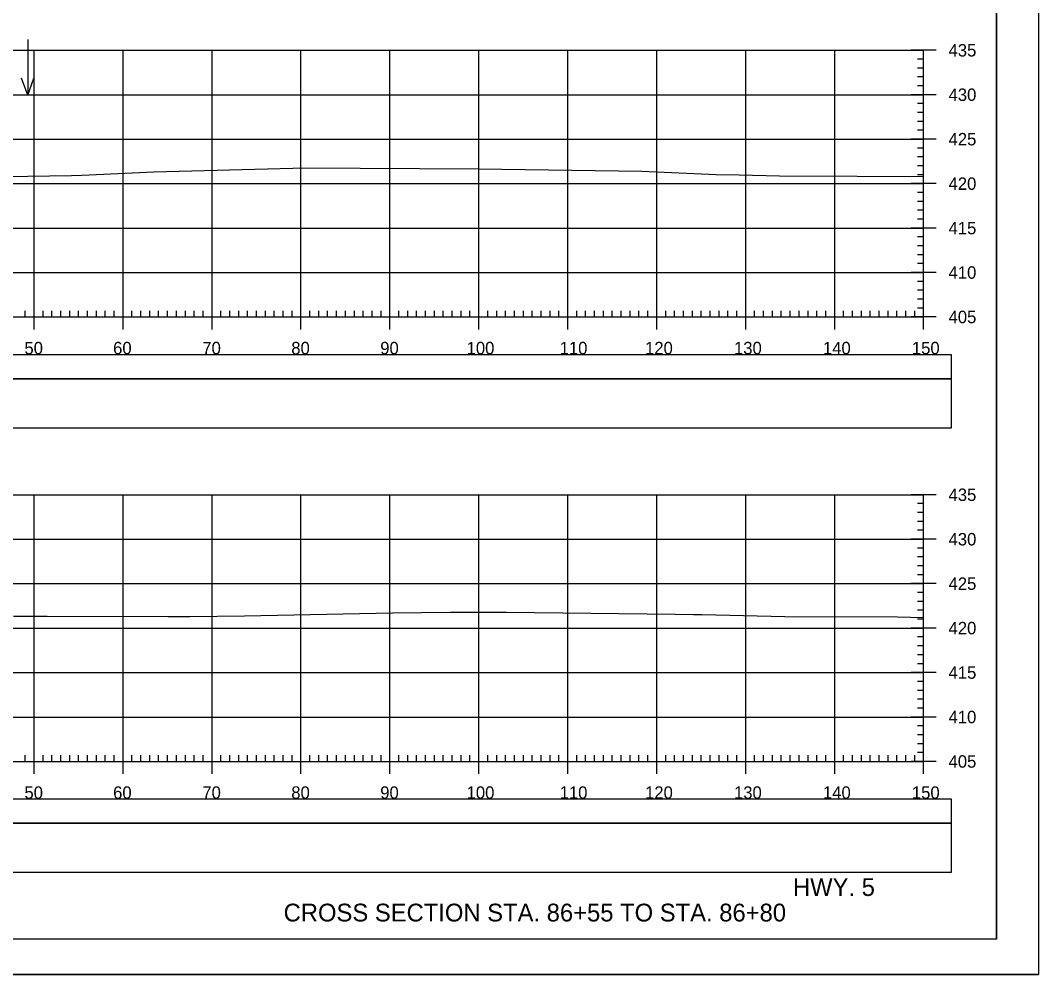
# Model space of a CAD drawing. Extents: x 1371057 to 1372761, y 380005 to 390517.
# Drawn here: x 1371276 to 1371390.5, y 388325.3 to 388432.6 of the extents above; entities that cross this region are included whole.
import ezdxf

# ---------------------------------------------------------------- set-up
doc = ezdxf.new("R2010")
doc.units = 0
for name, color, linetype in [('R_Axis', 7, 'Continuous'), ('R_Axis Annot', 7, 'Continuous'), ('R_Border', 7, 'Continuous'), ('R_Detour', 7, 'Continuous'), ('R_Dimension', 7, 'Continuous'), ('R_Draft', 7, 'Continuous'), ('R_Exist Surface', 7, 'Continuous'), ('R_Grid', 7, 'Continuous'), ('R_No Plot', 7, 'Continuous'), ('R_Water Annot', 7, 'Continuous')]:
    doc.layers.add(name, color=color, linetype=linetype)

msp = doc.modelspace()

# ---------------------------------------------------------------- linework, layer by layer
at = {"layer": 'R_Axis'}
for p, q in [((1371378.93, 388429.24), (1371376.13, 388429.24)), ((1371377.53, 388399.24), (1371377.53, 388429.24)), ((1371377.53, 388428.24), (1371376.83, 388428.24)), ((1371377.53, 388427.24), (1371376.83, 388427.24)), ((1371377.53, 388426.24), (1371376.83, 388426.24)), ((1371377.53, 388425.24), (1371376.83, 388425.24)), ((1371378.93, 388424.24), (1371376.13, 388424.24)), ((1371377.53, 388423.24), (1371376.83, 388423.24)), ((1371377.53, 388422.24), (1371376.83, 388422.24)), ((1371377.53, 388421.24), (1371376.83, 388421.24)), ((1371377.53, 388420.24), (1371376.83, 388420.24)), ((1371378.93, 388419.24), (1371376.13, 388419.24)), ((1371377.53, 388418.24), (1371376.83, 388418.24)), ((1371377.53, 388417.24), (1371376.83, 388417.24)), ((1371377.53, 388416.24), (1371376.83, 388416.24)), ((1371378.93, 388414.24), (1371376.13, 388414.24)), ((1371377.53, 388415.24), (1371376.83, 388415.24)), ((1371377.53, 388413.24), (1371376.83, 388413.24)), ((1371377.53, 388412.24), (1371376.83, 388412.24)), ((1371377.53, 388411.24), (1371376.83, 388411.24)), ((1371377.53, 388410.24), (1371376.83, 388410.24)), ((1371378.93, 388409.24), (1371376.13, 388409.24)), ((1371377.53, 388408.24), (1371376.83, 388408.24)), ((1371377.53, 388407.24), (1371376.83, 388407.24)), ((1371377.53, 388406.24), (1371376.83, 388406.24)), ((1371377.53, 388405.24), (1371376.83, 388405.24)), ((1371378.93, 388404.24), (1371376.13, 388404.24)), ((1371377.53, 388403.24), (1371376.83, 388403.24)), ((1371377.53, 388402.24), (1371376.83, 388402.24)), ((1371277.53, 388397.84), (1371277.53, 388400.64)), ((1371287.53, 388397.84), (1371287.53, 388400.64)), ((1371297.53, 388397.84), (1371297.53, 388400.64)), ((1371307.53, 388397.84), (1371307.53, 388400.64)), ((1371317.53, 388397.84), (1371317.53, 388400.64)), ((1371327.53, 388397.84), (1371327.53, 388400.64)), ((1371337.53, 388397.84), (1371337.53, 388400.64)), ((1371347.53, 388397.84), (1371347.53, 388400.64)), ((1371357.53, 388397.84), (1371357.53, 388400.64)), ((1371367.53, 388397.84), (1371367.53, 388400.64)), ((1371377.53, 388401.24), (1371376.83, 388401.24)), ((1371377.53, 388397.84), (1371377.53, 388400.64)), ((1371276.53, 388399.24), (1371276.53, 388399.94)), ((1371278.53, 388399.24), (1371278.53, 388399.94)), ((1371279.53, 388399.24), (1371279.53, 388399.94)), ((1371280.53, 388399.24), (1371280.53, 388399.94)), ((1371281.53, 388399.24), (1371281.53, 388399.94)), ((1371282.53, 388399.24), (1371282.53, 388399.94)), ((1371283.53, 388399.24), (1371283.53, 388399.94)), ((1371284.53, 388399.24), (1371284.53, 388399.94)), ((1371285.53, 388399.24), (1371285.53, 388399.94)), ((1371286.53, 388399.24), (1371286.53, 388399.94)), ((1371288.53, 388399.24), (1371288.53, 388399.94)), ((1371289.53, 388399.24), (1371289.53, 388399.94)), ((1371290.53, 388399.24), (1371290.53, 388399.94)), ((1371291.53, 388399.24), (1371291.53, 388399.94)), ((1371292.53, 388399.24), (1371292.53, 388399.94)), ((1371293.53, 388399.24), (1371293.53, 388399.94)), ((1371294.53, 388399.24), (1371294.53, 388399.94)), ((1371295.53, 388399.24), (1371295.53, 388399.94)), ((1371296.53, 388399.24), (1371296.53, 388399.94)), ((1371298.53, 388399.24), (1371298.53, 388399.94)), ((1371299.53, 388399.24), (1371299.53, 388399.94)), ((1371300.53, 388399.24), (1371300.53, 388399.94)), ((1371301.53, 388399.24), (1371301.53, 388399.94)), ((1371302.53, 388399.24), (1371302.53, 388399.94)), ((1371303.53, 388399.24), (1371303.53, 388399.94)), ((1371304.53, 388399.24), (1371304.53, 388399.94)), ((1371305.53, 388399.24), (1371305.53, 388399.94)), ((1371306.53, 388399.24), (1371306.53, 388399.94)), ((1371308.53, 388399.24), (1371308.53, 388399.94)), ((1371309.53, 388399.24), (1371309.53, 388399.94)), ((1371310.53, 388399.24), (1371310.53, 388399.94)), ((1371311.53, 388399.24), (1371311.53, 388399.94)), ((1371312.53, 388399.24), (1371312.53, 388399.94)), ((1371313.53, 388399.24), (1371313.53, 388399.94)), ((1371314.53, 388399.24), (1371314.53, 388399.94)), ((1371315.53, 388399.24), (1371315.53, 388399.94)), ((1371316.53, 388399.24), (1371316.53, 388399.94)), ((1371318.53, 388399.24), (1371318.53, 388399.94)), ((1371319.53, 388399.24), (1371319.53, 388399.94)), ((1371320.53, 388399.24), (1371320.53, 388399.94)), ((1371321.53, 388399.24), (1371321.53, 388399.94)), ((1371322.53, 388399.24), (1371322.53, 388399.94)), ((1371323.53, 388399.24), (1371323.53, 388399.94)), ((1371324.53, 388399.24), (1371324.53, 388399.94)), ((1371325.53, 388399.24), (1371325.53, 388399.94)), ((1371326.53, 388399.24), (1371326.53, 388399.94)), ((1371328.53, 388399.24), (1371328.53, 388399.94)), ((1371329.53, 388399.24), (1371329.53, 388399.94)), ((1371330.53, 388399.24), (1371330.53, 388399.94)), ((1371331.53, 388399.24), (1371331.53, 388399.94)), ((1371332.53, 388399.24), (1371332.53, 388399.94)), ((1371333.53, 388399.24), (1371333.53, 388399.94)), ((1371334.53, 388399.24), (1371334.53, 388399.94)), ((1371335.53, 388399.24), (1371335.53, 388399.94)), ((1371336.53, 388399.24), (1371336.53, 388399.94)), ((1371338.53, 388399.24), (1371338.53, 388399.94)), ((1371339.53, 388399.24), (1371339.53, 388399.94)), ((1371340.53, 388399.24), (1371340.53, 388399.94)), ((1371341.53, 388399.24), (1371341.53, 388399.94)), ((1371342.53, 388399.24), (1371342.53, 388399.94)), ((1371343.53, 388399.24), (1371343.53, 388399.94)), ((1371344.53, 388399.24), (1371344.53, 388399.94)), ((1371345.53, 388399.24), (1371345.53, 388399.94)), ((1371346.53, 388399.24), (1371346.53, 388399.94)), ((1371348.53, 388399.24), (1371348.53, 388399.94)), ((1371349.53, 388399.24), (1371349.53, 388399.94)), ((1371350.53, 388399.24), (1371350.53, 388399.94)), ((1371351.53, 388399.24), (1371351.53, 388399.94)), ((1371352.53, 388399.24), (1371352.53, 388399.94)), ((1371353.53, 388399.24), (1371353.53, 388399.94)), ((1371354.53, 388399.24), (1371354.53, 388399.94)), ((1371355.53, 388399.24), (1371355.53, 388399.94)), ((1371356.53, 388399.24), (1371356.53, 388399.94)), ((1371358.53, 388399.24), (1371358.53, 388399.94)), ((1371359.53, 388399.24), (1371359.53, 388399.94)), ((1371360.53, 388399.24), (1371360.53, 388399.94)), ((1371361.53, 388399.24), (1371361.53, 388399.94)), ((1371362.53, 388399.24), (1371362.53, 388399.94)), ((1371363.53, 388399.24), (1371363.53, 388399.94)), ((1371364.53, 388399.24), (1371364.53, 388399.94)), ((1371365.53, 388399.24), (1371365.53, 388399.94)), ((1371366.53, 388399.24), (1371366.53, 388399.94)), ((1371368.53, 388399.24), (1371368.53, 388399.94)), ((1371369.53, 388399.24), (1371369.53, 388399.94)), ((1371370.53, 388399.24), (1371370.53, 388399.94)), ((1371371.53, 388399.24), (1371371.53, 388399.94)), ((1371372.53, 388399.24), (1371372.53, 388399.94)), ((1371373.53, 388399.24), (1371373.53, 388399.94)), ((1371374.53, 388399.24), (1371374.53, 388399.94)), ((1371375.53, 388399.24), (1371375.53, 388399.94)), ((1371376.53, 388399.24), (1371376.53, 388399.94)), ((1371377.53, 388400.24), (1371376.83, 388400.24)), ((1371077.53, 388399.24), (1371377.53, 388399.24)), ((1371378.93, 388399.24), (1371376.13, 388399.24)), ((1371378.93, 388379.24), (1371376.13, 388379.24)), ((1371377.53, 388349.24), (1371377.53, 388379.24)), ((1371377.53, 388378.24), (1371376.83, 388378.24)), ((1371377.53, 388377.24), (1371376.83, 388377.24)), ((1371377.53, 388376.24), (1371376.83, 388376.24)), ((1371378.93, 388374.24), (1371376.13, 388374.24)), ((1371377.53, 388375.24), (1371376.83, 388375.24)), ((1371377.53, 388373.24), (1371376.83, 388373.24)), ((1371377.53, 388372.24), (1371376.83, 388372.24)), ((1371377.53, 388371.24), (1371376.83, 388371.24)), ((1371377.53, 388370.24), (1371376.83, 388370.24)), ((1371378.93, 388369.24), (1371376.13, 388369.24)), ((1371377.53, 388368.24), (1371376.83, 388368.24)), ((1371377.53, 388367.24), (1371376.83, 388367.24)), ((1371377.53, 388366.24), (1371376.83, 388366.24)), ((1371377.53, 388365.24), (1371376.83, 388365.24)), ((1371378.93, 388364.24), (1371376.13, 388364.24)), ((1371377.53, 388363.24), (1371376.83, 388363.24)), ((1371377.53, 388362.24), (1371376.83, 388362.24)), ((1371377.53, 388361.24), (1371376.83, 388361.24)), ((1371377.53, 388360.24), (1371376.83, 388360.24)), ((1371378.93, 388359.24), (1371376.13, 388359.24)), ((1371377.53, 388358.24), (1371376.83, 388358.24)), ((1371377.53, 388357.24), (1371376.83, 388357.24)), ((1371377.53, 388356.24), (1371376.83, 388356.24)), ((1371377.53, 388355.24), (1371376.83, 388355.24)), ((1371378.93, 388354.24), (1371376.13, 388354.24)), ((1371377.53, 388353.24), (1371376.83, 388353.24)), ((1371377.53, 388352.24), (1371376.83, 388352.24)), ((1371277.53, 388347.84), (1371277.53, 388350.64)), ((1371287.53, 388347.84), (1371287.53, 388350.64)), ((1371297.53, 388347.84), (1371297.53, 388350.64)), ((1371307.53, 388347.84), (1371307.53, 388350.64)), ((1371317.53, 388347.84), (1371317.53, 388350.64)), ((1371327.53, 388347.84), (1371327.53, 388350.64)), ((1371337.53, 388347.84), (1371337.53, 388350.64)), ((1371347.53, 388347.84), (1371347.53, 388350.64)), ((1371357.53, 388347.84), (1371357.53, 388350.64)), ((1371367.53, 388347.84), (1371367.53, 388350.64)), ((1371377.53, 388351.24), (1371376.83, 388351.24)), ((1371377.53, 388350.24), (1371376.83, 388350.24)), ((1371377.53, 388347.84), (1371377.53, 388350.64)), ((1371077.53, 388349.24), (1371377.53, 388349.24)), ((1371276.53, 388349.24), (1371276.53, 388349.94)), ((1371278.53, 388349.24), (1371278.53, 388349.94)), ((1371279.53, 388349.24), (1371279.53, 388349.94)), ((1371280.53, 388349.24), (1371280.53, 388349.94)), ((1371281.53, 388349.24), (1371281.53, 388349.94)), ((1371282.53, 388349.24), (1371282.53, 388349.94)), ((1371283.53, 388349.24), (1371283.53, 388349.94)), ((1371284.53, 388349.24), (1371284.53, 388349.94)), ((1371285.53, 388349.24), (1371285.53, 388349.94)), ((1371286.53, 388349.24), (1371286.53, 388349.94)), ((1371288.53, 388349.24), (1371288.53, 388349.94)), ((1371289.53, 388349.24), (1371289.53, 388349.94)), ((1371290.53, 388349.24), (1371290.53, 388349.94)), ((1371291.53, 388349.24), (1371291.53, 388349.94)), ((1371292.53, 388349.24), (1371292.53, 388349.94)), ((1371293.53, 388349.24), (1371293.53, 388349.94)), ((1371294.53, 388349.24), (1371294.53, 388349.94)), ((1371295.53, 388349.24), (1371295.53, 388349.94)), ((1371296.53, 388349.24), (1371296.53, 388349.94)), ((1371298.53, 388349.24), (1371298.53, 388349.94)), ((1371299.53, 388349.24), (1371299.53, 388349.94)), ((1371300.53, 388349.24), (1371300.53, 388349.94)), ((1371301.53, 388349.24), (1371301.53, 388349.94)), ((1371302.53, 388349.24), (1371302.53, 388349.94)), ((1371303.53, 388349.24), (1371303.53, 388349.94)), ((1371304.53, 388349.24), (1371304.53, 388349.94)), ((1371305.53, 388349.24), (1371305.53, 388349.94)), ((1371306.53, 388349.24), (1371306.53, 388349.94)), ((1371308.53, 388349.24), (1371308.53, 388349.94)), ((1371309.53, 388349.24), (1371309.53, 388349.94)), ((1371310.53, 388349.24), (1371310.53, 388349.94)), ((1371311.53, 388349.24), (1371311.53, 388349.94)), ((1371312.53, 388349.24), (1371312.53, 388349.94)), ((1371313.53, 388349.24), (1371313.53, 388349.94)), ((1371314.53, 388349.24), (1371314.53, 388349.94)), ((1371315.53, 388349.24), (1371315.53, 388349.94)), ((1371316.53, 388349.24), (1371316.53, 388349.94)), ((1371318.53, 388349.24), (1371318.53, 388349.94)), ((1371319.53, 388349.24), (1371319.53, 388349.94)), ((1371320.53, 388349.24), (1371320.53, 388349.94)), ((1371321.53, 388349.24), (1371321.53, 388349.94)), ((1371322.53, 388349.24), (1371322.53, 388349.94)), ((1371323.53, 388349.24), (1371323.53, 388349.94)), ((1371324.53, 388349.24), (1371324.53, 388349.94)), ((1371325.53, 388349.24), (1371325.53, 388349.94)), ((1371326.53, 388349.24), (1371326.53, 388349.94)), ((1371328.53, 388349.24), (1371328.53, 388349.94)), ((1371329.53, 388349.24), (1371329.53, 388349.94)), ((1371330.53, 388349.24), (1371330.53, 388349.94)), ((1371331.53, 388349.24), (1371331.53, 388349.94)), ((1371332.53, 388349.24), (1371332.53, 388349.94)), ((1371333.53, 388349.24), (1371333.53, 388349.94)), ((1371334.53, 388349.24), (1371334.53, 388349.94)), ((1371335.53, 388349.24), (1371335.53, 388349.94)), ((1371336.53, 388349.24), (1371336.53, 388349.94)), ((1371338.53, 388349.24), (1371338.53, 388349.94)), ((1371339.53, 388349.24), (1371339.53, 388349.94)), ((1371340.53, 388349.24), (1371340.53, 388349.94)), ((1371341.53, 388349.24), (1371341.53, 388349.94)), ((1371342.53, 388349.24), (1371342.53, 388349.94)), ((1371343.53, 388349.24), (1371343.53, 388349.94)), ((1371344.53, 388349.24), (1371344.53, 388349.94)), ((1371345.53, 388349.24), (1371345.53, 388349.94)), ((1371346.53, 388349.24), (1371346.53, 388349.94)), ((1371348.53, 388349.24), (1371348.53, 388349.94)), ((1371349.53, 388349.24), (1371349.53, 388349.94)), ((1371350.53, 388349.24), (1371350.53, 388349.94)), ((1371351.53, 388349.24), (1371351.53, 388349.94)), ((1371352.53, 388349.24), (1371352.53, 388349.94)), ((1371353.53, 388349.24), (1371353.53, 388349.94)), ((1371354.53, 388349.24), (1371354.53, 388349.94)), ((1371355.53, 388349.24), (1371355.53, 388349.94)), ((1371356.53, 388349.24), (1371356.53, 388349.94)), ((1371358.53, 388349.24), (1371358.53, 388349.94)), ((1371359.53, 388349.24), (1371359.53, 388349.94)), ((1371360.53, 388349.24), (1371360.53, 388349.94)), ((1371361.53, 388349.24), (1371361.53, 388349.94)), ((1371362.53, 388349.24), (1371362.53, 388349.94)), ((1371363.53, 388349.24), (1371363.53, 388349.94)), ((1371364.53, 388349.24), (1371364.53, 388349.94)), ((1371365.53, 388349.24), (1371365.53, 388349.94)), ((1371366.53, 388349.24), (1371366.53, 388349.94)), ((1371368.53, 388349.24), (1371368.53, 388349.94)), ((1371369.53, 388349.24), (1371369.53, 388349.94)), ((1371370.53, 388349.24), (1371370.53, 388349.94)), ((1371371.53, 388349.24), (1371371.53, 388349.94)), ((1371372.53, 388349.24), (1371372.53, 388349.94)), ((1371373.53, 388349.24), (1371373.53, 388349.94)), ((1371374.53, 388349.24), (1371374.53, 388349.94)), ((1371375.53, 388349.24), (1371375.53, 388349.94)), ((1371378.93, 388349.24), (1371376.13, 388349.24)), ((1371376.53, 388349.24), (1371376.53, 388349.94))]:
    msp.add_line(p, q, dxfattribs=at)
at = {"layer": 'R_Border'}
for q in [(1371385.71, 388534.7), (1371069.53, 388329.24)]:
    msp.add_line((1371385.71, 388329.24), q, dxfattribs=at)
at = {"layer": 'R_Detour'}
for points in [[(1371074.37, 388392.29), (1371380.68, 388392.29), (1371380.68, 388394.99), (1371074.37, 388394.99)], [(1371074.37, 388342.29), (1371380.68, 388342.29), (1371380.68, 388344.99), (1371074.37, 388344.99)]]:
    msp.add_lwpolyline(points, close=True, dxfattribs=at)
at = {"layer": 'R_Dimension'}
for points in [[(1371074.37, 388386.77), (1371380.68, 388386.77), (1371380.68, 388392.29), (1371074.37, 388392.29)], [(1371074.37, 388336.77), (1371380.68, 388336.77), (1371380.68, 388342.29), (1371074.37, 388342.29)]]:
    msp.add_lwpolyline(points, close=True, dxfattribs=at)
at = {"layer": 'R_Exist Surface'}
for points in [[(1371274.4, 388415.03), (1371279.25, 388415.1), (1371281.72, 388415.16), (1371282.88, 388415.2), (1371290.98, 388415.58), (1371306.61, 388415.98), (1371307.54, 388416), (1371327.49, 388415.91), (1371345.84, 388415.63), (1371354.21, 388415.25), (1371356.78, 388415.23), (1371361.33, 388415.13), (1371370.06, 388415.09), (1371377.53, 388415.06)], [(1371275.21, 388365.58), (1371278.99, 388365.58), (1371292.57, 388365.54), (1371295.09, 388365.55), (1371301.17, 388365.63), (1371317.8, 388365.95), (1371324.33, 388366.02), (1371330.65, 388366.03), (1371349.59, 388365.79), (1371351.67, 388365.78), (1371352.63, 388365.76), (1371361.92, 388365.55), (1371374.61, 388365.51), (1371377.53, 388365.44)]]:
    msp.add_lwpolyline(points, dxfattribs=at)
at = {"layer": 'R_Grid'}
for p, q in [((1371077.53, 388429.24), (1371377.53, 388429.24)), ((1371277.53, 388399.24), (1371277.53, 388429.24)), ((1371287.53, 388399.24), (1371287.53, 388429.24)), ((1371297.53, 388399.24), (1371297.53, 388429.24)), ((1371307.53, 388399.24), (1371307.53, 388429.24)), ((1371317.53, 388399.24), (1371317.53, 388429.24)), ((1371327.53, 388399.24), (1371327.53, 388429.24)), ((1371337.53, 388399.24), (1371337.53, 388429.24)), ((1371347.53, 388399.24), (1371347.53, 388429.24)), ((1371357.53, 388399.24), (1371357.53, 388429.24)), ((1371367.53, 388399.24), (1371367.53, 388429.24)), ((1371377.53, 388399.24), (1371377.53, 388429.24)), ((1371077.53, 388424.24), (1371377.53, 388424.24)), ((1371077.53, 388419.24), (1371377.53, 388419.24)), ((1371077.53, 388414.24), (1371377.53, 388414.24)), ((1371077.53, 388409.24), (1371377.53, 388409.24)), ((1371077.53, 388404.24), (1371377.53, 388404.24)), ((1371077.53, 388399.24), (1371377.53, 388399.24)), ((1371077.53, 388379.24), (1371377.53, 388379.24)), ((1371277.53, 388349.24), (1371277.53, 388379.24)), ((1371287.53, 388349.24), (1371287.53, 388379.24)), ((1371297.53, 388349.24), (1371297.53, 388379.24)), ((1371307.53, 388349.24), (1371307.53, 388379.24)), ((1371317.53, 388349.24), (1371317.53, 388379.24)), ((1371327.53, 388349.24), (1371327.53, 388379.24)), ((1371337.53, 388349.24), (1371337.53, 388379.24)), ((1371347.53, 388349.24), (1371347.53, 388379.24)), ((1371357.53, 388349.24), (1371357.53, 388379.24)), ((1371367.53, 388349.24), (1371367.53, 388379.24)), ((1371377.53, 388349.24), (1371377.53, 388379.24)), ((1371077.53, 388374.24), (1371377.53, 388374.24)), ((1371077.53, 388369.24), (1371377.53, 388369.24)), ((1371077.53, 388364.24), (1371377.53, 388364.24)), ((1371077.53, 388359.24), (1371377.53, 388359.24)), ((1371077.53, 388354.24), (1371377.53, 388354.24)), ((1371077.53, 388349.24), (1371377.53, 388349.24))]:
    msp.add_line(p, q, dxfattribs=at)
at = {"layer": 'R_No Plot'}
msp.add_line((1371057.12, 388325.26), (1371390.46, 388325.26), dxfattribs=at)
for points in [[(1371057.12, 388538.6), (1371390.46, 388538.6), (1371390.46, 388325.26), (1371057.12, 388325.26)], [(1371303.45, 388534.7), (1371323.07, 388534.7), (1371323.07, 388524.82), (1371339.18, 388524.82), (1371362.38, 388524.82), (1371362.5, 388496.66), (1371385.71, 388496.66), (1371385.71, 388329.24), (1371069.53, 388329.24), (1371069.53, 388534.7)]]:
    msp.add_lwpolyline(points, close=True, dxfattribs=at)
at = {"layer": 'R_Water Annot'}
for p, q in [((1371276.81, 388430.47), (1371276.81, 388424.19)), ((1371276.81, 388424.19), (1371276.11, 388426.11)), ((1371276.81, 388424.19), (1371277.51, 388426.11))]:
    msp.add_line(p, q, dxfattribs=at)

# ---------------------------------------------------------------- texts
at = {"layer": 'R_Axis Annot'}
for s, p in [('435', (1371380.33, 388428.54)), ('430', (1371380.33, 388423.54)), ('425', (1371380.33, 388418.54)), ('420', (1371380.33, 388413.54)), ('415', (1371380.33, 388408.54)), ('410', (1371380.33, 388403.54)), ('405', (1371380.33, 388398.54)), ('50', (1371276.44, 388395.04)), ('60', (1371286.41, 388395.04)), ('70', (1371296.44, 388395.04)), ('80', (1371306.44, 388395.04)), ('90', (1371316.44, 388395.04)), ('100', (1371326.15, 388395.04)), ('110', (1371336.61, 388395.04)), ('120', (1371346.21, 388395.04)), ('130', (1371356.21, 388395.04)), ('140', (1371366.21, 388395.04)), ('150', (1371376.21, 388395.04)), ('435', (1371380.33, 388378.54)), ('430', (1371380.33, 388373.54)), ('425', (1371380.33, 388368.54)), ('420', (1371380.33, 388363.54)), ('415', (1371380.33, 388358.54)), ('410', (1371380.33, 388353.54)), ('405', (1371380.33, 388348.54)), ('50', (1371276.44, 388345.04)), ('60', (1371286.41, 388345.04)), ('70', (1371296.44, 388345.04)), ('80', (1371306.44, 388345.04)), ('90', (1371316.44, 388345.04)), ('100', (1371326.15, 388345.04)), ('110', (1371336.61, 388345.04)), ('120', (1371346.21, 388345.04)), ('130', (1371356.21, 388345.04)), ('140', (1371366.21, 388345.04)), ('150', (1371376.21, 388345.04))]:
    msp.add_text(s, height=1.4, dxfattribs=at).set_placement(p)
at = {"layer": 'R_Draft'}
for s, p in [('HWY. 5', (1371362.84, 388334.11)), ('CROSS SECTION STA. 86+55 TO STA. 86+80', (1371305.58, 388331.24))]:
    msp.add_text(s, height=2, dxfattribs=at).set_placement(p)

doc.saveas('drawing.dxf')
